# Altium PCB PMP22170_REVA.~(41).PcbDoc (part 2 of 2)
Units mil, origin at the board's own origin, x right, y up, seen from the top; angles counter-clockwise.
Board outline 4950 x 3450 mil, 2 copper layers (Top Layer, Bottom Layer), stack 62 mil thick; 75 components, 28 nets, 158 pads, 70 vias.
Unrouted connection lines stored in the file: 122.
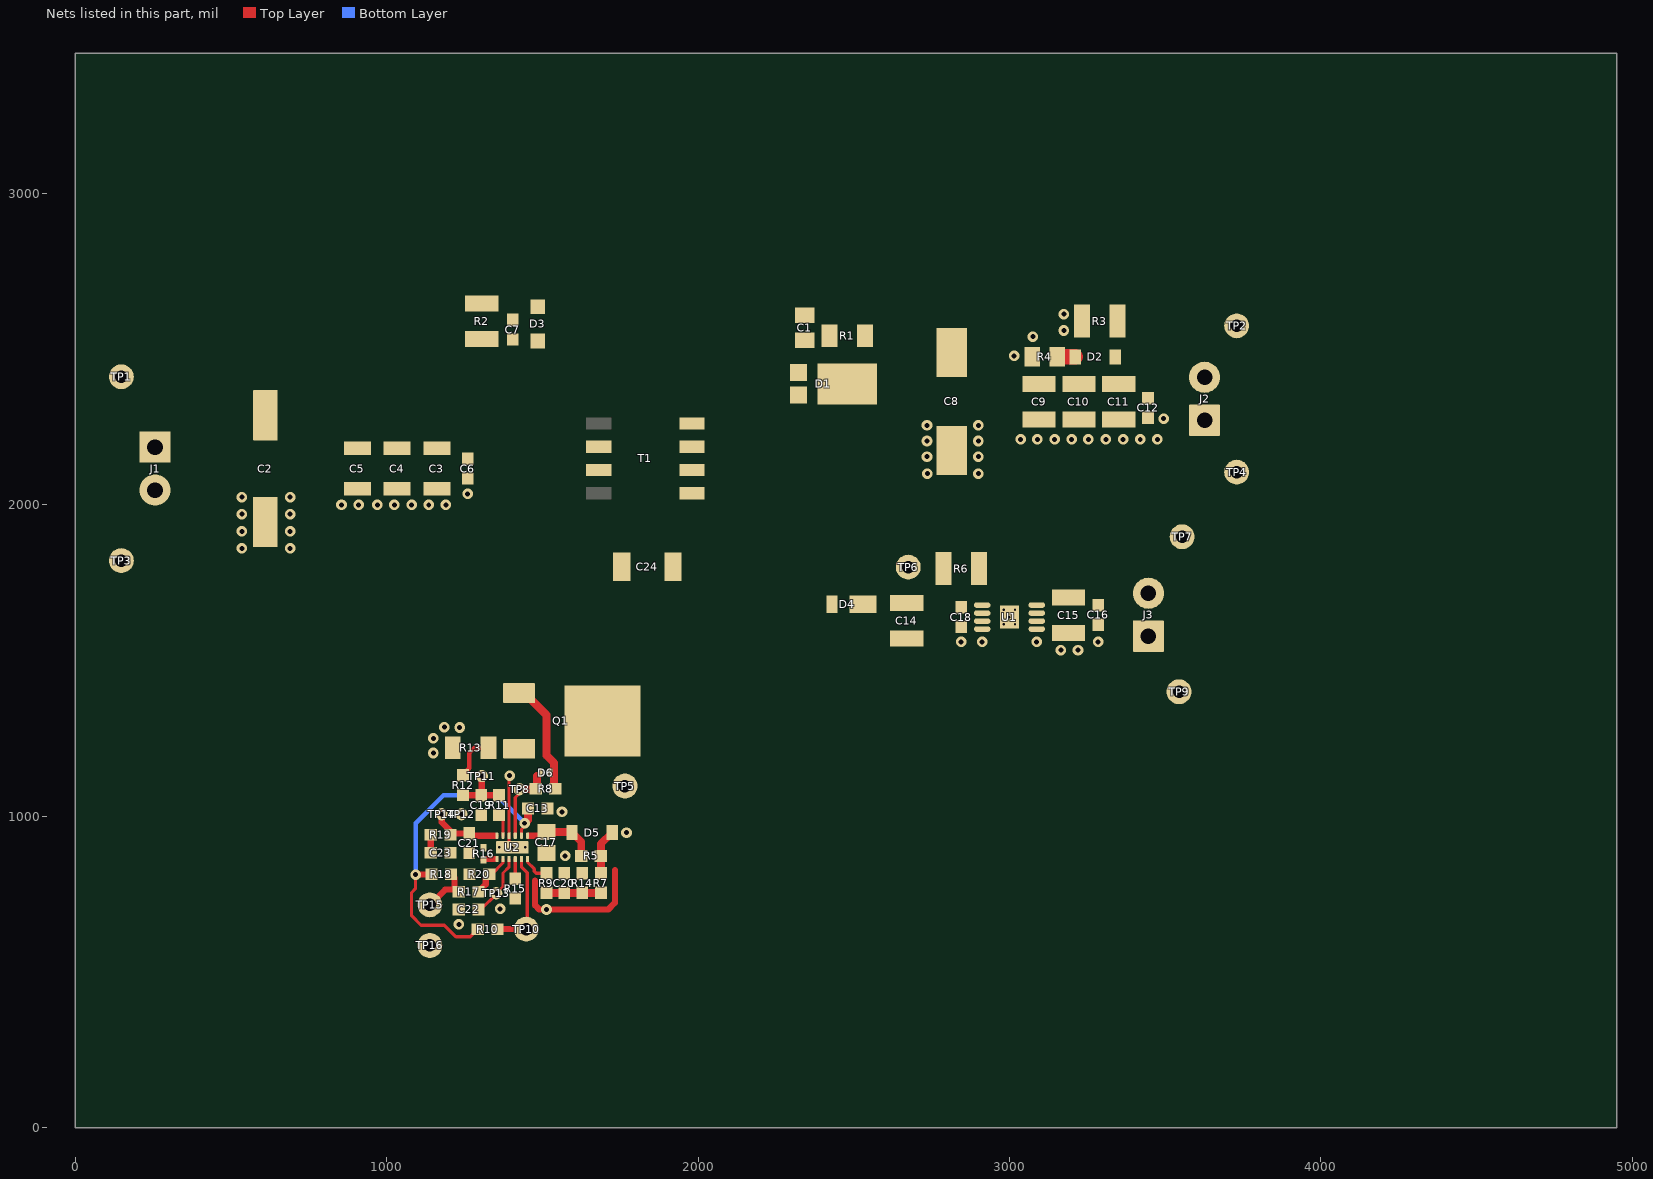
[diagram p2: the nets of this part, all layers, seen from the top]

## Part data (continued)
TP15: library part CMP-0055140-1, "Test Point, Miniature, Orange, TH", Color=Orange, Manufacturer=Keystone, Supplier Part Number 1=36-5003-ND
U1: library part CMP-0013313-4, "300mA High-Voltage Ultra-Low-Iq Low-Dropout (LDO) Regulator, DGN0008D (VSSOP-8)", Alternate Manufacturer="Texas Instruments"
U2: library part CMP-0081538-1, "Automotive Grade 2.2-MHz Wide Input Non-synchronous Boost Controller, DSS0012C (WSON-12)", Alternate Manufacturer="Texas Instruments", Alternate PartNumber=LM5155QDSSRQ1

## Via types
v1: diameter 34, hole 16, Top Layer to Bottom Layer, 62 vias
v2: diameter 19.68, hole 7.87, Top Layer to Bottom Layer, 8 vias

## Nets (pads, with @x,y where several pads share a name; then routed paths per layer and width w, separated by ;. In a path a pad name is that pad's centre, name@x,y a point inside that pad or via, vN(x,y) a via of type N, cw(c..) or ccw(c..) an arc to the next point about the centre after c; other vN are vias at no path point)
GND: C2.1 C3.2 C4.2 C5.2 C6.2 C13.2 C14.2 C15.2 C16.2 C17.2 C18.2 C19.2 C20.2 C21.2 C22.2 C23.2 C24.2 J1.2 J3.1 R6.1 R13.1 R14.1 R15.1 R16.1 R20.1 T1.8 TP3.1 TP9.1 TP12.1 TP16.1 U1.3 U1.4 U1.5 U1.6 U1.7 U1.9 U2.4 U2.13@1403.03,899.98 | length 690.3
  Top Layer w10: v1(1395,1130) 1392.28,1127.28 1392.28,938.29 U2.4@1393.19,937.38 1393.19,909.82 v2(1403.03,899.98)
  Top Layer w20: 1476.46,792.38 1476.46,713.98 1489.97,700.46 v1(1513.03,700.46) 1711.11,700.46 1733.03,722.38 1733.03,827.38
  other v1: 1231.65,652.38 1364.53,702.38 1573.03,872.38 1240,1006.3 1563.03,1014.12 1150,1202.98 1150,1250 1234.06,1285 1185,1285.91 3165,1533.43 3220,1533.43 2845,1560 2911.93,1560 3087.11,1560 3285,1560 535,1860 690,1860 535,1915 690,1915 535,1970 690,1970 854.76,1999.87 909.76,1999.87 969.76,1999.87 1024.76,1999.87 1080,1999.87 1135,1999.87 1189.76,1999.87 535,2025 690,2025 1260,2035
  other v2: 1360.71,899.98 1445.35,899.98 2982.28,1615.94 3017.72,1615.94 3000,1639.57 2982.28,1663.19 3017.72,1663.19
GND2: C8.2 C9.2 C10.2 C11.2 C12.2 C24.1 J2.1 R3.1 R4.1 T1.6 TP4.1
  other v1: 2736.22,2100 2900,2100 2735,2155 2900,2155 2735,2205 2900,2205 3035.94,2210 3089.76,2210 3144.76,2210 3199.76,2210 3253.19,2210 3309.76,2210 3364.76,2210 3420,2210 3475,2210 2735,2255 2900,2255 3495,2276.59 3015,2478.36 3075.32,2540 3174.76,2560 3174.76,2612.48
NetC1_1: C1.1 R1.1
NetC1_2: C1.2 D1.1 D1.2 T1.5
NetC2_2: C2.2 C3.1 C4.1 C5.1 C6.1 C7.1 D5.2 J1.1 R2.2 R5.2 R7.2 T1.2 TP1.1 | length 145.7
  Top Layer w25: R7.2@1688.07,816.83 1687.72,817.19 R5.2@1687.72,872.38 1687.72,911.1 D5.2@1724,947.38
  other v1: 1770,947.38
NetC7_2: C7.2 D3.1 R2.1
NetC8_1: C8.1 C9.1 C10.1 C11.1 C12.1 D1.3 D2.1 J2.2 R1.2 R3.2 TP2.1
NetC13_1: C13.1 C14.1 C18.1 D4.1 R6.2 R10.1 R18.2 TP6.1 U1.1 U1.2 U2.2 | length 1125.5
  Top Layer w10: v1(1093.03,812.38) 1093.03,768.18 1080,755.15 1080,680 1110,650 1185,650 1221.95,613.05 1268.35,613.05 R10.1@1292.68,637.38 ; U2.2@1432.56,937.38 1432.56,957.44 1443.03,967.92 v1(1443.03,977.38)
  Top Layer w20: v1(1093.03,812.38) 1141.99,812.38 R18.2@1143.48,813.88
  Top Layer w25: v1(1443.03,977.38) 1453.5,987.86 C13.1@1453.5,1025
  Bottom Layer w15: v1(1093.03,812.38) 1093.03,978.03 1182.27,1067.27 1353.15,1067.27 v1(1443.03,977.38)
NetC15_1: C15.1 C16.1 J3.2 TP7.1 U1.8
NetC17_1: C17.1 D5.1 R5.1 U2.1 | length 235.8
  Top Layer w10: U2.1@1452.24,937.38 1458.03,937.38
  Top Layer w20: 1458.03,937.38 1501.14,937.38 C17.1@1513.07,949.31
  Top Layer w25: C17.1@1513.07,949.31 1593.13,949.31 D5.1@1595.06,947.38 1624.72,917.72 R5.1@1624.72,872.38
NetC19_1: C19.1 R11.2 R12.1 TP11.1 | length 178.8
  Top Layer w20: R12.1@1245,1068.5 1246.24,1067.27 C19.1@1303.03,1067.27 ; v1(1305.47,1128.84) 1305.47,1069.71 C19.1@1303.03,1067.27 ; R11.2@1360.71,1067.27 C19.1@1303.03,1067.27
NetC20_1: C20.1 R7.1 R9.1 R14.2 | length 175
  Top Layer w25: R9.1@1513.03,753.84 C20.1@1570.03,753.84 R7.1@1688.07,753.84
NetC21_1: C21.1 R19.2 TP14.1 U2.6 | length 231
  Top Layer w10: 1345.94,937.38 U2.6@1353.82,937.38
  Top Layer w20: v1(1176.67,1006.3) 1176.67,980.79 1204.53,952.93 R19.2@1204.53,940.89 1208.52,944.88 C21.1@1264.52,944.88 1272.02,937.38 1345.94,937.38
NetC22_1: C22.1 TP13.1 U2.9 | length 207.4
  Top Layer w10: C22.1@1294.65,700.46 1302.25,700.46 1351.73,749.94 v1(1351.73,752.38) 1373.5,774.16 1373.5,817.58 1393.19,837.27 U2.9@1393.19,862.58
NetC23_1: C23.1 R19.1 | length 58.5
  Top Layer w20: C23.1@1141.54,882.38 R19.1@1141.54,940.89
NetD2_2: D2.2 R4.2 | length 57.9
  Top Layer w50: R4.2@3153.19,2475 D2.2@3211.12,2475
NetD3_2: D3.2 Q1.2 T1.3 TP5.1
NetD4_2: D4.2 T1.7
NetD6_1: D6.1 R8.2 TP8.1 U2.3 | length 265.8
  Top Layer w10: U2.3@1412.87,937.38 1412.87,1060.14 1426.46,1073.72 v1(1426.46,1086.52)
  Top Layer w15: 1482.44,1128.84 D6.1@1495.1,1138.2
  Top Layer w25: v1(1426.46,1086.52) 1477.34,1086.52 R8.2@1478.5,1087.68 1482.44,1091.62 1482.44,1128.84
NetD6_2: D6.2 Q1.1 R8.1 | length 366
  Top Layer w25: Q1.1@1425.39,1395.67 1442.36,1395.67 1513.07,1324.96 1513.07,1195.28 1537.56,1170.79 1537.56,1091.62 R8.1@1541.5,1087.68
NetQ1_3: Q1.3 R12.2 R13.2 | length 148.1
  Top Layer w15: R12.2@1245,1131.5 1255,1141.5 1255,1143.9 1265,1153.9 1265,1202.98 1282.02,1220 R13.2@1326.28,1220
NetR9_2: R9.2 U2.12 | length 90.3
  Top Layer w10: U2.12@1452.24,862.58 1452.24,852.41 1473.7,830.95 1473.7,823.05 1479.92,816.83 R9.2@1513.03,816.83
NetR11_1: R11.1 U2.5 | length 72.2
  Top Layer w10: R11.1@1360.71,1004.27 1373.5,991.48 U2.5@1373.5,937.38
NetR15_2: R15.2 U2.10 | length 63.7
  Top Layer w10: R15.2@1412.87,798.88 U2.10@1412.87,862.58
NetR16_2: R16.2 U2.7 | length 43.8
  Top Layer w10: 1345.96,862.58 U2.7@1353.82,862.58
  Top Layer w20: R16.2@1311.38,859.25 1314.7,862.58 1345.96,862.58
NetR17_1: R17.1 R18.1 TP15.1 | length 169.3
  Top Layer w20: TP15.1@1138.58,715.45 1187.58,764.45 1211.6,764.45 R17.1@1218.03,770.89 ; R18.1@1206.48,813.88 1218.03,802.32 R17.1@1218.03,770.89 ; R17.1@1231.54,757.38 R17.1@1218.03,770.89
NetR17_2: R17.2 R20.2 U2.8 | length 142.5
  Top Layer w10: R20.2@1329.09,813.88 1336.94,813.88 1373.5,850.45 U2.8@1373.5,862.58
  Top Layer w20: R17.2@1294.53,757.38 1318.03,780.89 1318.03,802.82 R20.2@1329.09,813.88
PG: R10.2 TP10.1 U2.11 | length 326.8
  Top Layer w10: U2.11@1432.56,862.58 1432.56,837.27 1451.5,818.33 1451.5,640.85 TP10.1@1448.03,637.38
  Top Layer w20: R10.2@1355.67,637.38 TP10.1@1448.03,637.38
pads on no net: T1.1 T1.4 U2.13@1376.06,899.98 U2.13@1430,899.98

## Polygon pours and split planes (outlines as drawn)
NetC2_2 on Top Layer "TOP_LAYER_NETC2_2_P016" (solid, remove dead copper, pour order 16): 70,2330
NetC2_2 on Top Layer "TOP_LAYER_NETC2_2_P014" (solid, remove dead copper, pour order 14): 130,2116.35 1278.52,2116.35 1278.54,2116.37 1278.54,2221.46 1250,2250 900,2250 689.54,2460.46 135.46,2460.46 100,2425 100,2145
NetQ1_3 on Top Layer "TOP_LAYER_NETQ1_3_P012" (solid, remove dead copper, pour order 12): 1476.46,1263.54 1470,1270 1305,1270 1300,1265 1300,1175.98 1305.47,1170.51 1305.47,1170 1467.66,1170 1476.46,1178.79
NetQ1_3 on Top Layer "TOP_LAYER_NETQ1_3_P010" (solid, remove dead copper, pour order 10): 1425.39,1216.14
NetC15_1 on Top Layer "TOP_LAYER_NETC15_1_P008" (solid, remove dead copper, pour order 8): 3059.04,1671.86 3059.04,1720 3129.04,1790 3554.45,1790 3554.45,1670.22 3531.18,1646.95 3154.9,1646.95 3136.85,1665 3136.54,1664.68 3066.22,1664.68
NetC13_1 on Top Layer "TOP_LAYER_NETC13_1_P006" (solid, remove dead copper, pour order 6): 2805,1680
NetC13_1 on Top Layer "TOP_LAYER_NETC13_1_P004" (solid, remove dead copper, pour order 4): 2825,1647.24 2941.04,1647.24 2941.04,1696.04 2932.09,1705 2825,1705
NetC8_1 on Top Layer "TOP_LAYER_NETC8_1_P002" (solid, remove dead copper, pour order 2): 2765,2570 2765,2320 3740.31,2320 3770,2349.69 3770,2594.61 3721.46,2643.15 3320,2643.15 3320,2540 3265,2485 3265,2437.4 3251.1,2423.5 3016.5,2423.5 2870,2570

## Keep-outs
Keep-Out Layer:
  text ".Layer_Name" at 577,-858.49 h60

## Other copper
Top Layer:
  text ".Layer_Name" at 577,-858.49 h60
Bottom Layer:
  text ".Layer_Name" at 577,-858.49 h60

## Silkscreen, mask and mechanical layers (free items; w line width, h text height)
Top Overlay:
  text "'.PRJ_Number'.PCB_Rev" at 3503.94,187.01 h108.27
  text ".Layer_Name" at 577,-858.49 h60
Bottom Overlay:
  text ".Layer_Name" at 577,-858.49 h60
Top Paste:
  text ".Layer_Name" at 577,-858.49 h60
Bottom Paste:
  text ".Layer_Name" at 577,-858.49 h60
Top Solder:
  text ".Layer_Name" at 577,-858.49 h60
  text ".Layer_Name" at 577,-858.49 h60
Bottom Solder:
  text ".Layer_Name" at 577,-858.49 h60
Drill Guide:
  text ".Layer_Name" at 577,-858.49 h60
M1 Board Outline:
  the board outline again, w10
  text ".Layer_Name" at 577,-858.49 h60
M2 Board Dimensions:
  rectangle: 0,-275 125,-150
  rectangle: 125,-400 500,-275
  lines w7: 0,-275 1000,-275 ; 125,-400 125,-150 ; 250,-400 250,-150 ; 500,-400 500,-150 ; 750,-400 750,-150 ; 0,-400 1000,-400 1000,-150 0,-150 0,-400
  text ".Layer_Name" at 577,-858.49 h60
M3 3D STEP Top:
  text ".Layer_Name" at 577,-858.49 h60
M4 3D STEP Bottom:
  text ".Layer_Name" at 577,-858.49 h60
M5 Assembly Top:
  lines w10: -292,-930.17 6308,-930.17 ; -292,-726.83 6310,-726.83 ; -292,-523.5 -292,-1133.5 3713,-1133.5 6310,-1133.5 6310,-523.5 -291.5,-523.5 -291.5,-1133.5 1284,-1133.5 ; 2173,-1133.5 2173,-523.5 ; 3440,-726.83 3440,-523.5 ; 4280,-726.83 4280,-523.5 ; 4902,-1140 4902,-937.17
  text "COMPONENTS MARKED 'DNP' SHOULD NOT BE POPULATED." at 1153.5,-318.5 h60
  text "ASSEMBLY VARIANT:" at 1153,-434 h60
  text ".VariantName" at 2189,-434 h60
  text "PCB VIEWED FROM TOP SIDE" at -228.5,-655.67 h60
  text "BOARD #:" at 2248,-655.67 h60
  text ".PRJ_Number" at 2793.5,-655.67 h60
  text "REV:" at 3638,-655.67 h60
  text ".PCB_Rev" at 3929.5,-655.67 h60
  text "SVN REV:" at 4476,-655.67 h60
  text ".VersionControl_RevNumber" at 4982,-655.67 h60
  text "TID #:" at 2248,-859 h60
  text ".TID" at 2793.5,-859 h60
  text "PLOT NAME =" at -228.5,-1064.34 h60
  text ".plot_File_Name" at 577,-1064.34 h60
  text "GENERATED    :" at 2250,-1064.34 h60
  text ".Print_Date" at 3119.5,-1064.34 h60
  text ".Print_Time" at 3848.5,-1064.34 h60
  text "TEXAS INSTRUMENTS" at 5113,-1064.34 h60
M6 Assembly Bottom:
  lines w10: -292.5,-727.33 6309.5,-727.33 ; -290.5,-930.67 6309.5,-930.67 ; 1115.5,-1140.5 1115.5,-937.67 ; 1737.5,-727.33 1737.5,-524 ; 2577.5,-727.33 2577.5,-524 ; 3844.5,-1134 3844.5,-524 ; 4733.5,-1134 6309,-1134 6309,-524 -292.5,-524 -292.5,-1134 2304.5,-1134 6309.5,-1134 6309.5,-524
  text "COMPONENTS MARKED 'DNP' SHOULD NOT BE POPULATED." at 6102,-318 h60
  text ".VariantName" at 5058,-434 h60
  text "ASSEMBLY VARIANT:" at 6097,-434 h60
  text ".VersionControl_RevNumber" at 1035.5,-656.17 h60
  text "SVN REV:" at 1541.5,-656.17 h60
  text ".PCB_Rev" at 2088,-656.17 h60
  text "REV:" at 2379.5,-656.17 h60
  text ".PRJ_Number" at 3224,-656.17 h60
  text "BOARD #:" at 3769.5,-656.17 h60
  text "PCB VIEWED FROM BOTTOM SIDE" at 6246,-656.17 h60
  text ".TID" at 3224,-859.5 h60
  text "TID #:" at 3769.5,-859.5 h60
  text "TEXAS INSTRUMENTS" at 904.5,-1064.84 h60
  text ".Print_Time" at 2169,-1064.84 h60
  text ".Print_Date" at 2898,-1064.84 h60
  text "GENERATED    :" at 3767.5,-1064.84 h60
  text ".plot_File_Name" at 5440.5,-1064.84 h60
  text "PLOT NAME =" at 6246,-1064.84 h60
M9 Title Sheet:
  drawing of 57 lines, arcs and shapes, not listed
  text "1" at 739.84,8036.5 h70
  text "2" at 3235.5,8036.5 h70
  text "3" at 5724.84,8036.5 h70
  text "4" at 8231.51,8036.5 h70
  text "5" at 10730.5,8036.5 h70
  text "6" at 13235.5,8036.5 h70
  text "A" at -416.5,6893.5 h70
  text "A" at 14383.5,6893.5 h70
  text "B" at -416.5,4513.5 h70
  text "B" at 14383.5,4513.5 h70
  text "C" at -416.5,2138.5 h70
  text "C" at 14383.5,2138.5 h70
  text "PROJECT TITLE:" at 11343.5,277.5 h45
  text ".PRJ_Title" at 11393.5,144.17 h70
  text "DESIGNED FOR:" at 11343.5,-23.5 h45
  text ".PRJ_Customer" at 11393.5,-163.5 h70
  text "D" at -416.5,-231.5 h70
  text "D" at 14383.5,-231.5 h70
  text "FILE NAME:" at 11343.5,-323.5 h45
  text ".PCB_File_Name_No_Path" at 11393.5,-443.5 h70
  text "Texas Instruments (TI) and/or its licensors do not warrant the accuracy or completeness of this specification" at 6374,-605.34 h45
  text "ENGINEER:" at 11343.5,-613.5 h45
  text "LAYOUT BY:" at 12848.5,-613.5 h45
  text "or any information contained therein. TI and/or its licensors do not warrant that this design will meet" at 6329.01,-718 h45
  text ".PRJ_Engineer" at 11393.5,-768.49 h70
  text ".PCB_Layout" at 12899,-768.49 h70
  text "the specifications, will be suitable for your application or fit for any particular purpose, or will operate in" at 6329.01,-830.67 h45
  text ".Layer_Name" at 577,-858.49 h60
  text "ALTIUM DESIGNER VERSION:" at 12848.5,-923.5 h45
  text "an implementation. TI and/or its licensors do not warrant that the design is production worthy. You should" at 6329.01,-943.33 h45
  text "completely validate and test your design implementation to confirm the system functionality for your application." at 6374,-1056 h45
  text ".print_Scale" at 11393.5,-1056.83 h70
  text ".Application_BuildNumber" at 12899,-1056.83 h70
  text "1" at 739.84,-1263.5 h70
  text "2" at 3235.5,-1263.5 h70
  text "3" at 5724.84,-1263.5 h70
  text "4" at 8231.51,-1263.5 h70
  text "5" at 10730.5,-1263.5 h70
  text "6" at 13235.5,-1263.5 h70
M10 Fab Notes:
  drawing of 189 lines, arcs and shapes, not listed
  text "DESIGN INFORMATION" at 12382.02,6356.17 h60
  text "MIN. TRACK WIDTH:" at 11737.46,6224.05 h60
  text "8" at 12833.7,6224.05 h60
  text "MIL" at 12988.46,6224.05 h60
  text "MIN. CLEARANCE:" at 11737.46,6099.92 h60
  text "0.2" at 12773.7,6099.93 h60
  text "mm" at 12988.46,6099.92 h60
  text "MIN. VIA PAD SIZE:" at 11737.46,5975.8 h60
  text "24" at 12803.71,5975.8 h60
  text "MIL" at 12988.46,5975.8 h60
  text "0.05mm (2MIL)" at 12432.46,5845.9 h60
  text "MINIMUM ANNULAR RING" at 11408.23,5837.67 h60
  text "EXTERNAL" at 13140.46,5837.67 h60
  text "PER" at 11608.23,5727.55 h60
  text "IPC-D-275 CLASS 2 LEVEL C" at 11828.23,5727.54 h60
  text "MIL, HOLES" at 13316.46,5627.07 h60
  text "+/-" at 12924,5618.48 h60
  text "+/-" at 13778,5618.48 h60
  text "REGISTRATION TOLERANCES:" at 11408.23,5617.42 h60
  text "METAL" at 12608,5617.42 h60
  text "5" at 13184.2,5617.42 h60
  text "3" at 14017.2,5617.42 h60
  text "MIL" at 14133.46,5617.42 h60
  text "HOLE SIZE TOLERANCE (UNLESS OTHERWISE SPECIFIED):" at 11408.23,5519.1 h60
  text "+/-" at 13778,5516.23 h60
  text "3" at 14017.2,5515.17 h60
  text "MIL" at 14133.46,5515.17 h60
  text "MATERIAL:" at 11333.46,5377.52 h60
  text "FR-4 High Tg" at 12319.9,5249 h60
  text "X" at 12175.46,5241.01 h60
  text "FR-408" at 11754.46,5236.49 h60
  text "OTHER" at 13242.46,5236.49 h60
  text "62 MIL (1.6mm) +/-10%" at 12074.56,5093.46 h60
  text "X" at 11954.46,5091.01 h60
  text "THICKNESS:" at 11408.23,5085.24 h60
  text "OTHER" at 13359.46,5085.24 h60
  text "TOLERANCE:" at 11408.23,4946.92 h60
  text "X" at 12256.46,4946.92 h60
  text "ANSI IPC-6012 TYPE 3 CLASS 2" at 12434.48,4946.92 h60
  text "OTHER +/-" at 12434.46,4802.73 h60
  text "BOW & TWIST:" at 11408.23,4657.54 h60
  text "X" at 12256.46,4657.54 h60
  text "ANSI IPC-6012 TYPE 3 CLASS 2" at 12434.48,4657.54 h60
  text "OTHER +/-" at 12434.46,4510.85 h60
  text "DRILLING:" at 11333.46,4380.23 h60
  text "NC_DRILL FILES" at 13094.46,4275.04 h60
  text "REFERENCE:" at 11408.23,4271.1 h60
  text "X" at 12065.46,4271.01 h60
  text "AS SHOWN" at 12243.46,4271.1 h60
  text "X" at 12966.46,4271.1 h60
  text "OTHER" at 13392.46,4128.85 h60
  text "PTH COPPER THICKNESS:" at 11407.91,4125.32 h60
  text "X" at 12547.14,4125.32 h60
  text "20-30 um" at 12675.14,4125.32 h60
  text "BOARD FINISH:" at 11333.46,3977.73 h60
  text "SILKSCREEN:" at 11488.68,3867.6 h60
  text "X" at 12446.46,3867.6 h60
  text "TOP" at 12563.46,3867.6 h60
  text "X" at 12956.46,3867.6 h60
  text "BOTTOM" at 13074.46,3867.6 h60
  text "SILKSCREEN COLOR:" at 11488.68,3712.41 h60
  text "X" at 12445.46,3712.41 h60
  text "WHITE" at 12563.46,3712.41 h60
  text "OTHER" at 13074.46,3712.41 h60
  text "X" at 12576.46,3568.96 h60
  text "GREEN" at 12694.46,3568.96 h60
  text "OTHER" at 13312.46,3568.96 h60
  text "SOLDER RESIST COLOR:" at 11488.68,3562.1 h60
  text "X" at 12576.46,3414.71 h60
  text "MATTE" at 12694.46,3414.71 h60
  text "SEMI-GLOSS" at 13312,3414.07 h60
  text "IMMERSION GOLD (ENIG)" at 12394.46,3241.94 h60
  text "ENEPIG" at 13732,3234.72 h60
  text "SURFACE FINISH:" at 11333.46,3233.72 h60
  text "X" at 12216.46,3233.72 h60
  text "IMM. TIN/SILVER OR EQUIV" at 11663,3096.4 h60
  text "OTHER" at 13094.46,3092.47 h60
  text "ARRAY/PANEL:" at 11333.46,2937.09 h60
  text "CUT AND TRIM PER M1 BOARD OUTLINE" at 12394.46,2928.87 h60
  text "N.C. ROUTE" at 12394.46,2792.9 h60
  text "X" at 13082.46,2792.9 h60
  text "V. SCORE" at 13260.46,2792.9 h60
  text "CERTIFICATION:" at 11333.46,2663.77 h60
  text "MATERIALS AND WORKMANSHIP FOR ALL PCBS" at 12058.46,2663.77 h60
  text "TO MEET OR EXCEED THE REQUIREMENTS OF:" at 12058.46,2569.71 h60
  text "X" at 11695.97,2441.08 h60
  text "ANSI IPC-A-600F CLASS ->" at 11823.96,2441.08 h60
  text "X" at 13471.97,2441.08 h60
  text "2" at 13581.96,2441.08 h60
  text "1" at 13266.96,2439.58 h60
  text "3" at 13935.96,2439.58 h60
  text "X" at 12507.97,2293.39 h60
  text "RoHS" at 12635.96,2293.39 h60
  text "OTHER" at 13280.36,2293.39 h60
  text "PER ORDER" at 13677.42,2293.39 h60
  text "ALL BOARDS MUST MEET OR EXCEED UL94-V0 REQUIREMENTS." at 11361,2139.57 h60
  text "PCB MUST BEAR THE UL94V-0 UL REGISTERED MATERIAL ID NUMBER" at 11361,2023.5 h60
  text "ADDITIONAL REQUIREMENTS:" at 11333.46,1854.08 h60
  text "MICROSECTION:" at 11408.23,1746.95 h60
  text "YES" at 12313.96,1746.95 h60
  text "REQUIRED" at 13175.46,1602.62 h60
  text "BARE BOARD ELEC. TEST:" at 11408.23,1599.76 h60
  text "NONE" at 12713.96,1599.76 h60
  text "X" at 13057.46,1599.76 h60
  text "PER ORDER" at 13767.46,1599.76 h60
  text "XX MIL VIAS REQUIRE NON-CONDUCTIVE FILL AND PLANARIZE" at 11576.38,1394.82 h59
  text "XX MIL VIAS REQUIRE CONDUCTIVE FILL AND PLANARIZE" at 11584.38,1290.84 h60
  text "OUTER XX MIL TRACES REQUIRE 50 OHM SINGLE-ENDED IMPEDANCE" at 11583.39,1127.46 h58
  text "LAYER 2 & 3 (INNER LAYERS) XX MIL WIDE, XX MIL SPACE / TRACES REQUIRE 100 OHM DIFFERENTIAL IMPEDANCE" at 11575.39,891.74 h60
  text ".Layer_Name" at 577,-858.49 h60
M11 Gerber Information:
  lines w10: -292,-930.17 6308,-930.17 ; -292,-726.83 6310,-726.83 ; -292,-523.5 -292,-1133.5 3713,-1133.5 6310,-1133.5 6310,-523.5 -291.5,-523.5 -291.5,-1133.5 1284,-1133.5 ; 2173,-1133.5 2173,-523.5 ; 3440,-726.83 3440,-523.5 ; 4280,-726.83 4280,-523.5 ; 4902,-1140 4902,-937.17
  text "ALL ARTWORK VIEWED FROM TOP SIDE" at -228.5,-655.67 h60
  text "BOARD #:" at 2248,-655.67 h60
  text ".PRJ_Number" at 2793.5,-655.67 h60
  text "REV:" at 3638,-655.67 h60
  text ".PCB_Rev" at 3929.5,-655.67 h60
  text "SVN REV:" at 4476,-655.67 h60
  text ".VersionControl_RevNumber" at 4982,-655.67 h60
  text "LAYER NAME =" at -228.5,-858.49 h60
  text "TID #:" at 2248,-859 h60
  text ".TID" at 2793.5,-859 h60
  text "PLOT NAME =" at -228.5,-1064.34 h60
  text ".plot_File_Name" at 577,-1064.34 h60
  text "GENERATED    :" at 2250,-1064.34 h60
  text ".Print_Date" at 3119.5,-1064.34 h60
  text ".Print_Time" at 3848.5,-1064.34 h60
  text "TEXAS INSTRUMENTS" at 5113,-1064.34 h60
M12 Stackup:
  drawing of 191 lines, arcs and shapes, not listed
  text "Layer" at 9811.59,7784.94 h60
  text "Name" at 10221.51,7784.94 h60
  text "Material" at 11151.25,7784.94 h60
  text "Thickness" at 12011.02,7784.94 h60
  text "Constant" at 12660.85,7784.94 h60
  text "Board Layer Stack" at 13230.71,7784.94 h60
  text "1" at 9811.59,7664.94 h60
  text "Top Overlay" at 10221.51,7664.94 h60
  text "2" at 9811.59,7544.94 h60
  text "Top Solder" at 10221.51,7544.94 h60
  text "Solder Resist" at 11151.25,7544.94 h60
  text "0.40mil" at 12011.02,7544.94 h60
  text "3.5" at 12660.85,7544.94 h60
  text "3" at 9811.59,7424.94 h60
  text "Top Layer" at 10221.51,7424.94 h60
  text "Copper" at 11151.25,7424.94 h60
  text "1.40mil" at 12011.02,7424.94 h60
  text "4" at 9811.59,7304.94 h60
  text "Dielectric1" at 10221.51,7304.94 h60
  text "FR-4" at 11151.25,7304.94 h60
  text "59.20mil" at 12011.02,7304.94 h60
  text "4.8" at 12660.85,7304.94 h60
  text "5" at 9811.59,7184.94 h60
  text "Bottom Layer" at 10221.51,7184.94 h60
  text "Copper" at 11151.25,7184.94 h60
  text "1.40mil" at 12011.02,7184.94 h60
  text "6" at 9811.59,7064.94 h60
  text "Bottom Solder" at 10221.51,7064.94 h60
  text "Solder Resist" at 11151.25,7064.94 h60
  text "0.40mil" at 12011.02,7064.94 h60
  text "3.5" at 12660.85,7064.94 h60
  text "7" at 9811.59,6944.94 h60
  text "Bottom Overlay" at 10221.51,6944.94 h60
  text ".Layer_Name" at 577,-858.49 h60
M13 Component Bodies Top:
  text ".Layer_Name" at 577,-858.49 h60
M14 Component Bodies Bottom:
  text ".Layer_Name" at 577,-858.49 h60
M15 Courtyards Top:
  text ".Layer_Name" at 577,-858.49 h60
M16 Courtyards Bottom:
  text ".Layer_Name" at 577,-858.49 h60
Drill Drawing:
  circle w10: c5363.72,3195.96 r27.63
  lines w10: 5336.09,2974.95 5391.34,2974.95 5363.72,2919.7 5336.09,2974.95 ; 5336.09,3044.02 5391.34,3044.02 5391.34,3099.27 5336.09,3099.27 5336.09,3044.02 ; 5336.09,3306.47 5349.9,3306.47 5363.72,3292.66 5377.53,3306.47 5391.34,3306.47 5377.53,3320.28 5391.34,3334.1 5377.53,3334.1 5363.72,3347.91 5349.9,3334.1 5336.09,3334.1 5349.9,3320.28 5336.09,3306.47
  lines w12: 5286,2882.4 8517.49,2882.4 ; 5286,3379.68 8517.49,3379.68 ; 5623.86,2758.08 5623.86,3504 ; 5955.86,2758.08 5955.86,3504 ; 6592.43,2758.08 6592.43,3504 ; 6851.57,2758.08 6851.57,3504 ; 7226.72,2758.08 7226.72,3504 ; 7951.05,2758.08 7951.05,3504 ; 5286,2758.08 8517.49,2758.08 8517.49,3504 5286,3504 5286,2758.08
  text "Symbol" at 5360.59,3416.98 h72
  text "Quantity" at 5661.16,3416.98 h72
  text "Finished Hole Size" at 5993.16,3416.98 h72
  text "Plated" at 6629.72,3416.98 h72
  text "Hole Type" at 6888.86,3416.98 h72
  text "Drill Layer Pair" at 7264.02,3416.98 h72
  text "Hole Tolerance" at 7988.35,3416.98 h72
  text "8" at 5661.16,3292.66 h60
  text "7.87mil (0.200mm)" at 5993.16,3292.66 h60
  text "PTH" at 6629.72,3292.66 h60
  text "Round" at 6888.86,3292.66 h60
  text "Top Layer - Bottom Layer" at 7264.02,3292.66 h60
  text "46" at 5661.16,3168.34 h60
  text "16.00mil (0.406mm)" at 5993.16,3168.34 h60
  text "PTH" at 6629.72,3168.34 h60
  text "Round" at 6888.86,3168.34 h60
  text "Top Layer - Bottom Layer" at 7264.02,3168.34 h60
  text "11" at 5661.16,3044.02 h60
  text "40.00mil (1.016mm)" at 5993.16,3044.02 h60
  text "PTH" at 6629.72,3044.02 h60
  text "Round" at 6888.86,3044.02 h60
  text "Top Layer - Bottom Layer" at 7264.02,3044.02 h60
  text "6" at 5661.16,2919.7 h60
  text "50.00mil (1.270mm)" at 5993.16,2919.7 h60
  text "PTH" at 6629.72,2919.7 h60
  text "Round" at 6888.86,2919.7 h60
  text "Top Layer - Bottom Layer" at 7264.02,2919.7 h60
  text "71 Total" at 5661.16,2795.38 h60
  text ".Layer_Name" at 577,-858.49 h60
M17 Embedded Cavity:
  text ".Layer_Name" at 577,-858.49 h60
M18 Embedded Assembly:
  text ".Layer_Name" at 577,-858.49 h60
M19 Embedded Keepout:
  text ".Layer_Name" at 577,-858.49 h60

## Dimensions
0,-400 to 1000,-400 on M2 Board Dimensions
0,0 to 0,3450 on M2 Board Dimensions
0,0 to 4950,0 on M2 Board Dimensions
